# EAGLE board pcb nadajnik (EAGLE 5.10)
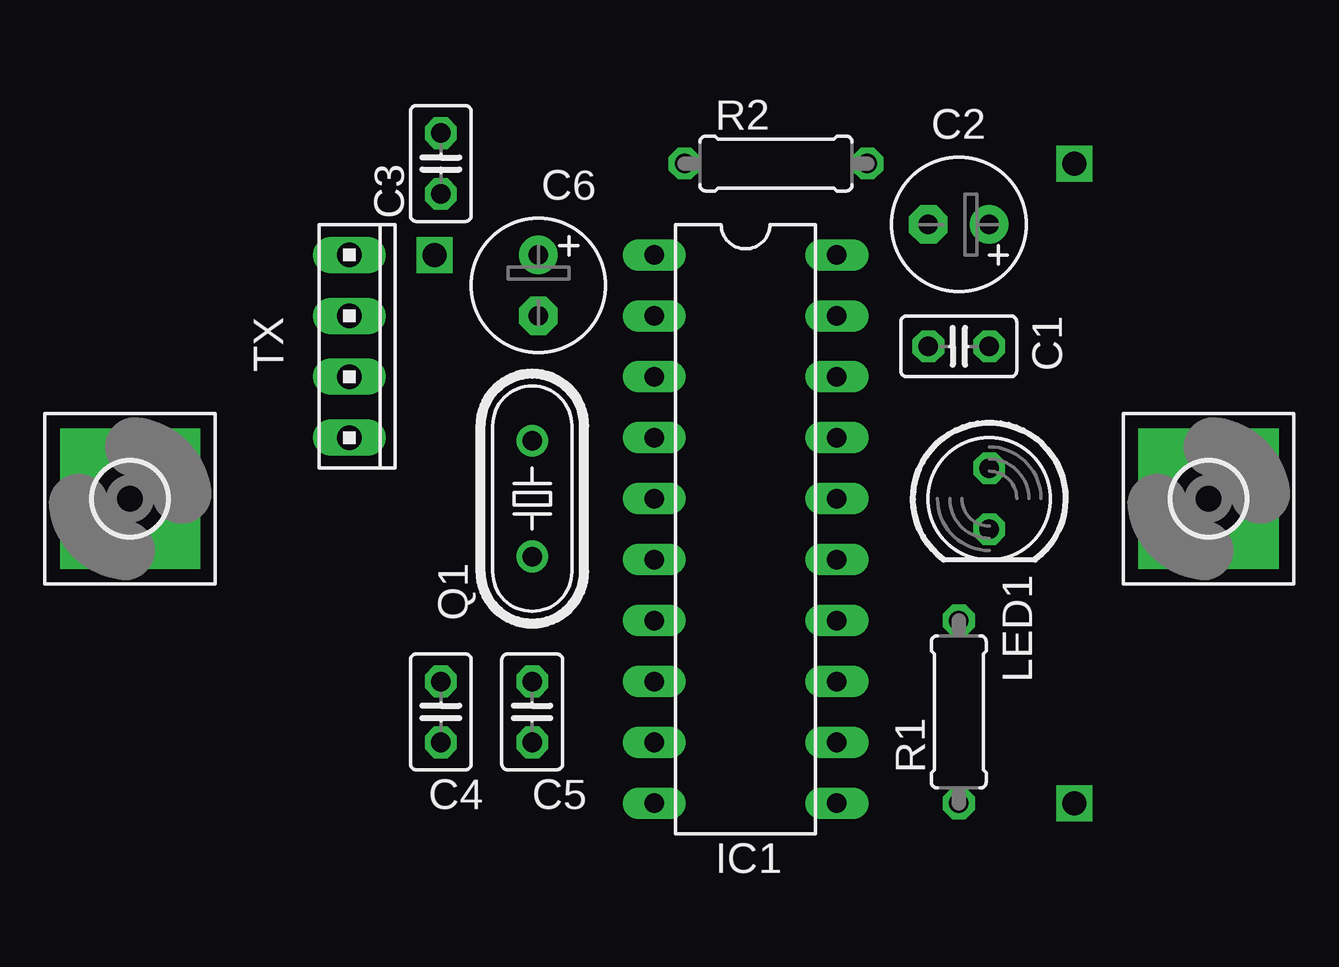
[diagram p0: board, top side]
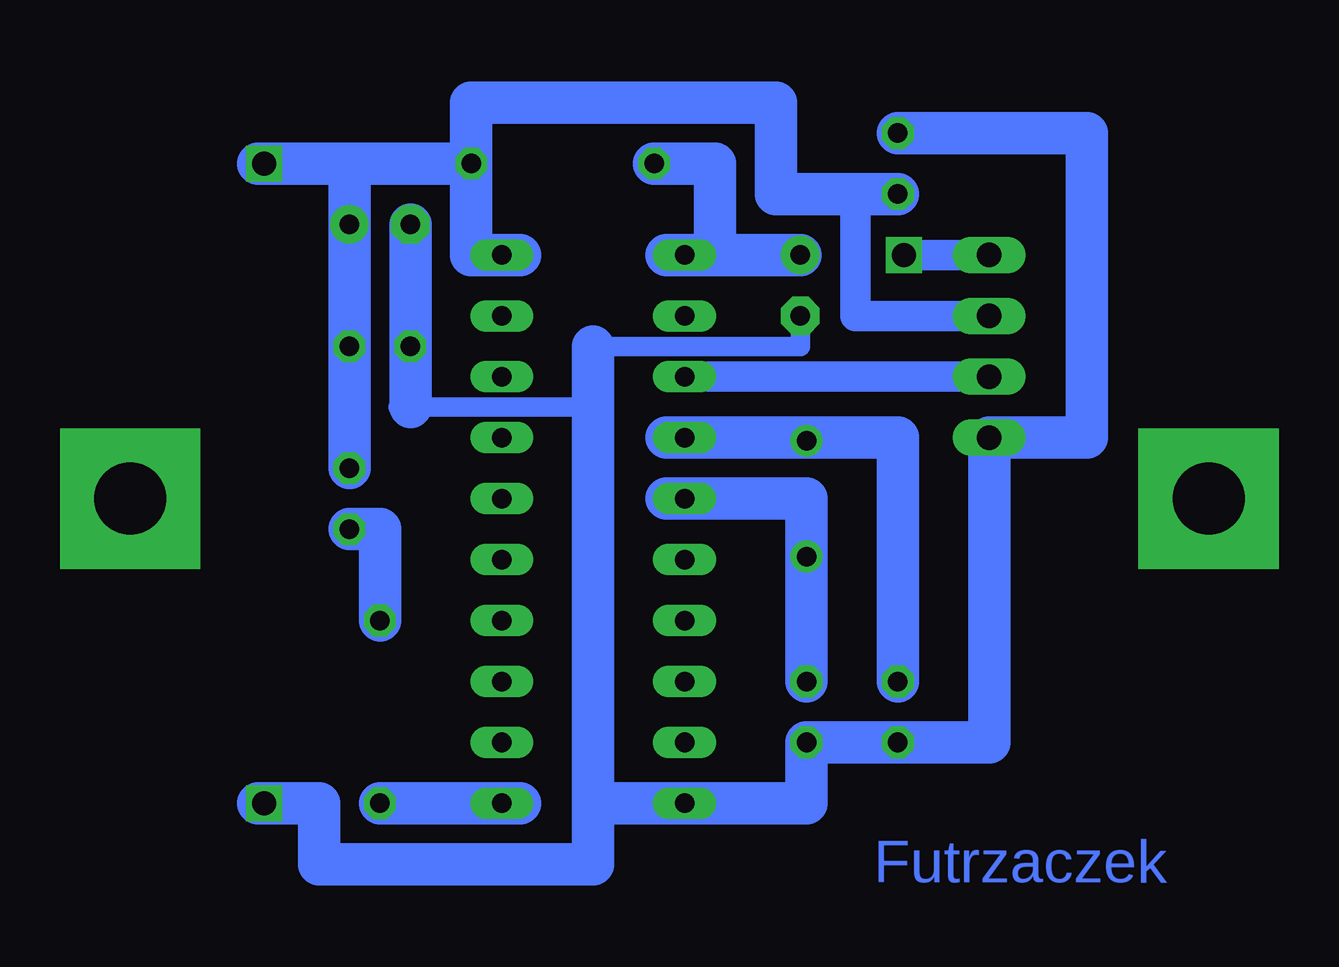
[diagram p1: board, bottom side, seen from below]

No outline drawn. Coordinates in mm, seen from the top.
Copper layers (1*16): Top 0.035mm / dielectric 1.5mm / Bottom 0.035mm
Design rules "default": minimum track width 10mil, minimum drill 24mil, track to track 8mil, track to pad 8mil, pad to pad 8mil, via to via 8mil, smd to smd 8mil, copper to edge 40mil, drill to drill 8mil, minimum pad ring 10mil, minimum via ring 8mil, stop-mask expansion 4mil, vias tented up to drill 0mil, thermal gap 10mil

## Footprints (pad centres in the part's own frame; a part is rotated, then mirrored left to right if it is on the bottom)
C025-025X050 = drill 0.813 octagon: 1 -1.27,0; 2 1.27,0
E2,5-6 = drill 0.813 pad 1.6 round: + -1.27,0 | drill 0.813 pad 1.6 octagon: - 1.27,0
3,0-PAD-SQUARE = drill 3 pad 5.842 square: B3,0 0,0
DIL20 = drill 0.813 long: 1 -11.43,-3.81; 2 -8.89,-3.81; 3 -6.35,-3.81; 4 -3.81,-3.81; 5 -1.27,-3.81; 6 1.27,-3.81; 7 3.81,-3.81; 8 6.35,-3.81; 9 8.89,-3.81; 10 11.43,-3.81; 11 11.43,3.81; 12 8.89,3.81; 13 6.35,3.81; 14 3.81,3.81; 15 1.27,3.81; 16 -1.27,3.81; 17 -3.81,3.81; 18 -6.35,3.81; 19 -8.89,3.81; 20 -11.43,3.81
LED5MM = drill 0.813 octagon: A -1.27,0; K 1.27,0
HC49/S = drill 0.813 round: 1 -2.413,0; 2 2.413,0
0207/7 = drill 0.813 octagon: 1 -3.81,0; 2 3.81,0
10X04MTA = drill 1.016 long: 1 3.81,0; 2 1.27,0; 3 -1.27,0; 4 -3.81,0

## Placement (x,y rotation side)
C1  [C025-025X050]  39.62,25.4 180 top
C2  [E2,5-6]  39.62,30.48 180 top
C3  [C025-025X050]  18.03,33.02 90 top
C4  [C025-025X050]  18.03,10.16 90 top
C5  [C025-025X050]  21.84,10.16 90 top
C6  [E2,5-6]  22.1,27.94 270 top
E$1  [3,0-PAD-SQUARE]  50.04,19.05 0 top
E$2  [3,0-PAD-SQUARE]  5.08,19.05 0 top
IC1  [DIL20]  30.73,17.78 270 top
LED1  [LED5MM]  40.89,19.05 270 top
Q1  [HC49/S]  21.84,19.05 90 top
R1  [0207/7]  39.62,10.16 90 top
R2  [0207/7]  32,33.02 0 top
TX  [10X04MTA]  14.22,25.4 270 top

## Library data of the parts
C1-C6 R1 R2 = rcl
E$1 E$2 = holes
IC1 = 40xx
LED1 = led
Q1 = crystal
TX = con-amp

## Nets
S$1: C6.+
S$2: C2.+ LED1.A TX.3
S$3: C4.2
S$4: C5.2
S$5: TX.2
S$6: C3.2 C4.1 C5.1 C6.- TX.1
S$7: TX.4
S$9: LED1.K R1.2
S$10: IC1.11 R1.1

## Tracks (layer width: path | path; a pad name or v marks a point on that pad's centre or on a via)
S$1
  Bottom 1.778: 28.19,33.02 25.65,33.02 25.65,29.21 26.92,29.21 | 26.92,29.21 27.69,29.21 | C6.+ 26.92,29.21
S$2
  Bottom 1.27: TX.3 19.81,26.67 19.81,31.75
  Bottom 1.778: LED1.A C2.+ 40.89,33.02 | 40.89,33.02 44.7,33.02 | 33.78,29.21 35.81,29.21 35.81,33.02 | 35.81,33.02 40.89,33.02 | 35.81,33.02 35.81,35.56 23.11,35.56 23.11,31.75 19.81,31.75 18.03,31.75
S$3
  Bottom 1.778: 27.69,21.59 18.03,21.59 C4.2
S$4
  Bottom 1.778: 27.69,19.05 21.84,19.05 C5.2
S$5
  Bottom 1.27: TX.2 27.43,24.13
S$6
  Bottom 0.813: C6.- 22.1,25.4 30.73,25.4
  Bottom 1.778: 30.73,6.35 30.73,25.4 | C3.2 10.16,34.29 10.16,21.59 TX.1 14.22,8.89 C4.1 C5.1 21.84,6.35 30.73,6.35 | 30.73,6.35 30.73,3.81 42.16,3.81 42.16,6.35 44.7,6.35
S$7  (via drill 1)
  Bottom 1.27: TX.4 v17.78,29.21
S$8  (via drill 1)
  other vias: 44.45,6.35
S$9
  Bottom 1.778: LED1.K 39.62,17.78 R1.2
S$10
  Bottom 1.778: R1.1 IC1.11 33.78,6.35
S$11
  Bottom 0.813: 30.99,22.86 38.35,22.86 38.86,22.86
  Bottom 1.778: 38.35,22.86 38.35,30.48
S$12  (via drill 1)
  other vias: 44.45,33.02

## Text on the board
Bottom: Futrzaczek
tValues: + | 4 | ANT | 1 | -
